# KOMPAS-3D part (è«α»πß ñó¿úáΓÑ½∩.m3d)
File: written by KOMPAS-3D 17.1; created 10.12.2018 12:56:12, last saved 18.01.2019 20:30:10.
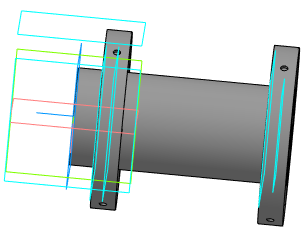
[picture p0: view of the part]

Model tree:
1. Тело корпуса
2. Операция вращения:1
     Угол 1 = 360
3. Направляющая замка
4. Вырезать элемент выдавливания:1
     Расстояние 1 = 5
5. Смещенная плоскость:2
     Расстояние = 19.5
6. Ключ замка
7. Вырезать элемент вращения:1
     Угол 1 = 90; Угол 2 = 90
8. Копия Ключа замка  (with: Вырезать элемент вращения:1, Смещенная плоскость:2)  (2 pattern instances)
     N 1 = 1; Шаг 1 = 10; Шаг 2 = 360; Номер 1 = 1
9. Стойки крепления движка
10. Операция выдавливания:1
     Расстояние 1 = 15.9
11. Копии стоек  (with: Операция выдавливания:1, Смещенная плоскость:2, Эскиз:6)  (3 pattern instances)
     N 1 = 1; Шаг 1 = 10; Шаг 2 = 360; Номер 1 = 1
12. Смещенная плоскость:4
     Расстояние = 10
13. Смещенная плоскость:5
     Расстояние = 67
14. Крепление вала к корпусу
15. Операция выдавливания:3
     Расстояние 2 = 10
16. Крепление вала к корпусу у замка
17. Операция выдавливания:4
     Расстояние 2 = 10
18. Скругление:1
     Радиус = 2
19. Скругление:2
     Радиус = 2
20. Скругление:3
     Радиус = 2
21. Скругление:4
     Радиус = 2
22. Скругление:5
     Радиус = 2
23. Скругление:7
     Радиус = 2
24. Скругление:8
     Радиус = 2
25. Скругление:9
     Радиус = 2
26. Скругление:11
     Радиус = 2
27. Скругление:12
     Радиус = 2
28. Смещенная плоскость:6
     Расстояние = 5
29. Отверстия крепления двигателя
30. Вырезать элемент выдавливания:2
     Расстояние 1 = 10
31. Смещенная плоскость:7
     Расстояние = 35.71
32. Смещенная плоскость:8
     Расстояние = 5
33. Крепежное отверстие 1
34. Вырезать элемент вращения:2
     Угол 1 = 360
35. Крепежное отверстие 2
36. Вырезать элемент вращения:3
     Угол 1 = 360
37. Крепежное отверстие 3
38. Вырезать элемент вращения:4
     Угол 1 = 360
39. Крепежное отверстие 4
40. Вырезать элемент вращения:5
     Угол 1 = 360
41. Крепежное отверстие 5
42. Вырезать элемент вращения:6
     Угол 1 = 360
43. Крепежное отверстие 7
44. Вырезать элемент вращения:7
     Угол 1 = 360
45. Грань замка
46. Операция выдавливания:5
     Расстояние 2 = 5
